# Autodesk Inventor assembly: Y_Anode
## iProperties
Shininess: 64.0
Length Units: 11269
Angle Units: 11279
Time Units: 11290
Mass Units: 11283
Length Display Precision: 3
Angle Display Precision: 2
Compacted: True
Created: 2003-02
Part Number: Y_Anode
Document SubType Name: Assembly
Designer: hofer_a
Density: 0.0
Volumn: 0.0
Area: 0.0
PropertySet Name: Model Information
Control State: 0
Master: False
Checked Out: False
Author: hofer_a
